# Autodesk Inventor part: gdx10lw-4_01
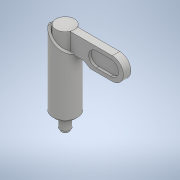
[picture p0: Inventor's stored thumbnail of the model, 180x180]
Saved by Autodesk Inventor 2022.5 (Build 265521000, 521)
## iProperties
Part Number: gdx10lw-4_01
Material: 一般
Document SubType Name: Modeling
Designer: ImaoCorp
Density: 1 g/cm^3
Appearance: 既定
Author: ImaoCorp
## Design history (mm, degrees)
feature "gdx10lw-4_01"
node "ソリッド1"
